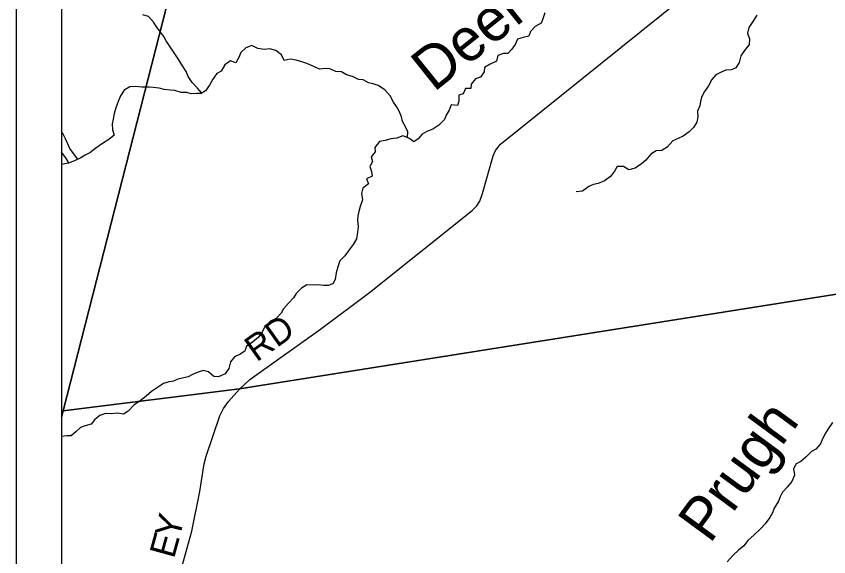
# Model space of a CAD drawing. Extents: x 0 to 36.5, y 0 to 25.3.
# Drawn here: x 2 to 3.798, y 15.97 to 17.166 of the extents above; entities that cross this region are included whole.
import ezdxf

# ---------------------------------------------------------------- set-up
doc = ezdxf.new("R2010")
doc.units = 0
for name, color, linetype in [('DV_X_Township_Line', 7, 'Continuous'), ('GM_X_Interstate_Route', 7, 'Continuous'), ('GM_X_Major_River', 7, 'Continuous'), ('GM_X_Major_River_Text', 7, 'Continuous'), ('GM_X_Minor_River', 7, 'Continuous'), ('GM_X_Minor_River_Text', 7, 'Continuous'), ('GM_X_Township_Road', 7, 'Continuous'), ('GM_X_Township_Road_Text', 7, 'Continuous'), ('SH_Cut_Line', 7, 'Continuous'), ('SH_Data', 7, 'Continuous')]:
    doc.layers.add(name, color=color, linetype=linetype)

msp = doc.modelspace()

# ---------------------------------------------------------------- linework, layer by layer
at = {"layer": 'DV_X_Township_Line'}
msp.add_lwpolyline([(4.5783, 20.9), (3.3366, 20.9), (3.2612, 20.6041), (2.8463, 19.037), (2.6265, 18.2595), (2.5271, 17.8912), (2.5226, 17.8751), (2.5165, 17.8524), (2.5144, 17.8445), (2.4192, 17.4891), (2.3437, 17.2326), (2.3403, 17.2198), (2.1039, 16.2931), (2.4938, 16.3413), (4.0938, 16.595), (4.8891, 16.7511), (5.1383, 16.6527), (6.6079, 15.9978)], dxfattribs=at)
msp.add_lwpolyline([(2.1, 16.2788), (2.1, 14.1), (8.9, 14.1), (8.9, 14.8674), (8.5228, 15.0526), (8.0723, 15.2737), (7.8139, 15.4027), (7.7814, 15.4189), (7.7552, 15.432), (7.703, 15.458), (6.8419, 15.8878), (6.6079, 15.9978), (5.1383, 16.6527), (4.8891, 16.7511), (4.0938, 16.595), (2.4938, 16.3413), (2.1039, 16.2931)], close=True, dxfattribs=at)
at = {"layer": 'GM_X_Interstate_Route'}
msp.add_lwpolyline([(2.1, 17.5234), (2.1, 16.2788), (2.1039, 16.2931), (2.3403, 17.2198), (2.3437, 17.2326), (2.4192, 17.4891)], close=True, dxfattribs=at)
at = {"layer": 'GM_X_Major_River'}
msp.add_lwpolyline([(3.1697, 17.174), (3.1651, 17.1608), (3.1612, 17.1509), (3.1482, 17.1434), (3.1375, 17.1329), (3.134, 17.1223), (3.1214, 17.119), (3.1089, 17.1153), (3.1038, 17.1039), (3.0965, 17.0937), (3.0877, 17.0839), (3.0782, 17.0836), (3.0653, 17.0796), (3.0622, 17.0671), (3.0484, 17.0603), (3.0362, 17.0532), (3.0354, 17.043), (3.0269, 17.0317), (3.0163, 17.0276), (3.0063, 17.0163), (3.0058, 17.0064), (2.9937, 17.0065), (2.9887, 16.9944), (2.9788, 16.9914), (2.979, 16.9785), (2.9759, 16.9687), (2.9623, 16.9703), (2.958, 16.9585), (2.951, 16.9476), (2.9472, 16.9377), (2.9349, 16.9253), (2.9216, 16.9167), (2.9082, 16.9115), (2.8979, 16.9051), (2.8895, 16.8953), (2.8796, 16.8882), (2.8683, 16.8966), (2.855, 16.9013), (2.8417, 16.8965), (2.8288, 16.8951), (2.8158, 16.8914), (2.8037, 16.8888), (2.7933, 16.8756)], dxfattribs=at)
at = {"layer": 'GM_X_Minor_River'}
for points in [[(2.3241, 17.1245), (2.3101, 17.1427), (2.3041, 17.1523), (2.2928, 17.166), (2.2803, 17.1696)], [(3.6383, 17.1689), (3.6298, 17.155), (3.621, 17.1414), (3.6178, 17.1288), (3.6219, 17.1163), (3.6218, 17.1034), (3.6129, 17.0928), (3.6033, 17.0784), (3.5994, 17.0641), (3.5921, 17.0523), (3.5822, 17.0479), (3.57, 17.0472), (3.5578, 17.0416), (3.5479, 17.0364), (3.5391, 17.0262), (3.5318, 17.0126), (3.5226, 17.0001), (3.516, 16.9873), (3.514, 16.9778), (3.5124, 16.9679), (3.5074, 16.9562), (3.5076, 16.944), (3.5056, 16.9319), (3.4983, 16.9202), (3.4887, 16.9108), (3.4757, 16.9006), (3.4662, 16.8961), (3.4529, 16.8902), (3.4402, 16.8766), (3.428, 16.8691), (3.4159, 16.8681), (3.4037, 16.861), (3.3926, 16.8474), (3.383, 16.8395), (3.3689, 16.8297), (3.3552, 16.8264), (3.3431, 16.8338), (3.3294, 16.8339), (3.3237, 16.8233), (3.3144, 16.8116), (3.3015, 16.8018), (3.2877, 16.7959), (3.2767, 16.7941), (3.2668, 16.7892), (3.2527, 16.7791), (3.239, 16.7773)], [(2.4104, 16.9961), (2.4007, 17.007), (2.3894, 17.0196), (2.3804, 17.033), (2.3756, 17.044), (2.3662, 17.0585), (2.3599, 17.0696), (2.3509, 17.0834), (2.3423, 17.0967), (2.3318, 17.1116), (2.3262, 17.1212), (2.3241, 17.1245)], [(2.8653, 16.8977), (2.8665, 16.9103), (2.8601, 16.9229), (2.8542, 16.9336), (2.852, 16.9439), (2.8475, 16.9564), (2.8416, 16.9664), (2.8348, 16.9759), (2.827, 16.99), (2.8153, 17.0038), (2.801, 17.0134), (2.7893, 17.0166), (2.7791, 17.0193), (2.7677, 17.0255), (2.7571, 17.0263), (2.7439, 17.0329), (2.7303, 17.0364), (2.7197, 17.0434), (2.7068, 17.0442), (2.694, 17.05), (2.6845, 17.0509), (2.6712, 17.0491), (2.6583, 17.0553), (2.6425, 17.0619), (2.6315, 17.0658), (2.6194, 17.0693), (2.6058, 17.0717), (2.5928, 17.0684), (2.5865, 17.0806), (2.5744, 17.0909), (2.5612, 17.0941), (2.549, 17.0931), (2.5346, 17.0947), (2.5214, 17.1013), (2.5081, 17.0961), (2.497, 17.0863), (2.4923, 17.0749), (2.4858, 17.0636), (2.4737, 17.0679), (2.4615, 17.0589), (2.4537, 17.0449), (2.4438, 17.0396), (2.435, 17.0268), (2.4273, 17.0136), (2.4188, 17.0011), (2.4093, 16.9955), (2.3998, 16.9956), (2.3873, 16.9949), (2.3774, 16.9977), (2.3645, 16.9978), (2.3505, 17.0021), (2.3411, 17.0025), (2.3274, 17.0042), (2.3161, 17.0069), (2.3032, 17.0086), (2.2939, 17.0097)], [(2.2939, 17.0097), (2.2779, 17.0097), (2.2646, 17.0105), (2.251, 17.0099), (2.2384, 17.0024), (2.2303, 16.9903), (2.2257, 16.9778), (2.2206, 16.9638), (2.2167, 16.9509), (2.2147, 16.9384), (2.2124, 16.9281), (2.2127, 16.9152), (2.2164, 16.903), (2.2049, 16.8936), (2.1908, 16.885), (2.1763, 16.8741), (2.1626, 16.8643), (2.1526, 16.8587), (2.1412, 16.8519), (2.1286, 16.846), (2.1157, 16.8411), (2.1039, 16.8386), (2.1, 16.8378)], [(2.1363, 16.8496), (2.1291, 16.8596), (2.1186, 16.8734), (2.1134, 16.8852), (2.1089, 16.8951), (2.1041, 16.9054), (2.1, 16.9113)], [(2.7933, 16.8756), (2.794, 16.8661), (2.7855, 16.8548), (2.7885, 16.8445), (2.7819, 16.8339), (2.7856, 16.8225), (2.7874, 16.8126), (2.7745, 16.8067), (2.7793, 16.7952), (2.7671, 16.7855), (2.7639, 16.7737), (2.7657, 16.7596), (2.761, 16.7453), (2.7579, 16.7343), (2.7555, 16.7248), (2.7551, 16.7153), (2.7561, 16.7001), (2.7548, 16.6883), (2.7524, 16.6739), (2.7451, 16.6611), (2.734, 16.646), (2.7267, 16.6362), (2.7156, 16.6249), (2.7117, 16.6116), (2.7077, 16.598), (2.7053, 16.5839), (2.7007, 16.5741), (2.6897, 16.57), (2.6802, 16.5701), (2.6669, 16.5714), (2.6567, 16.5707), (2.6426, 16.5716), (2.6312, 16.5644), (2.6189, 16.5528), (2.6131, 16.5426), (2.602, 16.5309), (2.5913, 16.5188), (2.5863, 16.509), (2.5752, 16.4969), (2.5622, 16.491), (2.5496, 16.4789), (2.5426, 16.465), (2.535, 16.4551), (2.5216, 16.4439), (2.5094, 16.4356), (2.5055, 16.4246), (2.4929, 16.4168), (2.4834, 16.4131), (2.4738, 16.4014), (2.4702, 16.3866), (2.4625, 16.3745), (2.4473, 16.3682), (2.4374, 16.3686), (2.4254, 16.3794), (2.4133, 16.3821), (2.4, 16.3777), (2.3901, 16.3732), (2.3801, 16.3684), (2.3573, 16.3629), (2.3478, 16.3588), (2.3379, 16.3573), (2.3254, 16.3536), (2.3124, 16.3446), (2.2994, 16.3353), (2.2876, 16.3251), (2.2742, 16.3146), (2.2601, 16.3056), (2.2474, 16.292), (2.2375, 16.2853), (2.2242, 16.2877), (2.2117, 16.2859), (2.1977, 16.2868), (2.1847, 16.2823), (2.174, 16.2733), (2.166, 16.2631), (2.1523, 16.2594), (2.1424, 16.2557), (2.1328, 16.2471), (2.1217, 16.2377), (2.1122, 16.2374), (2.1, 16.2357)], [(2.1166, 16.8415), (2.1097, 16.8529), (2.1, 16.8651)], [(3.8059, 16.2667), (3.7963, 16.2531), (3.7905, 16.2433), (3.7839, 16.2305), (3.7796, 16.2199), (3.7693, 16.2078), (3.759, 16.203), (3.7468, 16.1905), (3.7357, 16.1808), (3.7254, 16.1752), (3.7196, 16.1642), (3.7221, 16.1501), (3.7159, 16.1361), (3.7059, 16.1248), (3.6952, 16.1124), (3.6902, 16.1026), (3.6867, 16.0927), (3.6767, 16.0772), (3.6728, 16.067), (3.6674, 16.0564), (3.6567, 16.0425), (3.6463, 16.0315), (3.6325, 16.0184), (3.6184, 16.006), (3.6096, 15.9939), (3.5977, 15.9845), (3.5862, 15.9732), (3.5728, 15.9585)]]:
    msp.add_lwpolyline(points, dxfattribs=at)
at = {"layer": 'GM_X_Township_Road'}
for points in [[(2.5272, 16.3696), (2.6732, 16.4737), (2.7817, 16.5545), (3.0089, 16.7361), (3.0189, 16.7463), (3.0254, 16.7567), (3.0317, 16.7741), (3.055, 16.8575), (3.0601, 16.8689), (3.0713, 16.8835), (3.5173, 17.2429), (3.5586, 17.2771), (3.5726, 17.2899), (3.5758, 17.292)], [(2.494, 16.3408), (2.5166, 16.3621), (2.5272, 16.3696)], [(2.1961, 15.6605), (2.2376, 15.7131), (2.2696, 15.7589), (2.3252, 15.8486), (2.3463, 15.8865), (2.3626, 15.9333), (2.3881, 16.0266), (2.4061, 16.1141), (2.4156, 16.1754), (2.4201, 16.1926), (2.4502, 16.2815), (2.4585, 16.2981), (2.4693, 16.3132), (2.494, 16.3408)]]:
    msp.add_lwpolyline(points, dxfattribs=at)
at = {"layer": 'SH_Cut_Line'}
msp.add_lwpolyline([(3.3366, 20.9), (2.1, 20.9), (2.1, 16.2788), (2.1039, 16.2931), (2.3403, 17.2198), (2.3437, 17.2326), (2.4192, 17.4891), (2.5144, 17.8445), (2.5165, 17.8524), (2.5226, 17.8751), (2.5271, 17.8912), (2.6265, 18.2595), (2.8463, 19.037), (3.2612, 20.6041)], close=True, dxfattribs=at)
msp.add_lwpolyline([(4.4591, 20.9), (3.3366, 20.9), (3.2612, 20.6041), (2.8463, 19.037), (2.6265, 18.2595), (2.5271, 17.8912), (2.5226, 17.8751), (2.5165, 17.8524), (2.5144, 17.8445), (2.4192, 17.4891), (2.3437, 17.2326), (2.3403, 17.2198), (2.1039, 16.2931), (2.1, 16.2788), (2.1, 14.1), (8.9, 14.1), (8.9, 20.9), (6.1845, 20.9)], dxfattribs=at)
at = {"layer": 'SH_Data'}
for p, q in [((2, 21), (2, 14)), ((2.1, 20.9), (2.1, 14.1))]:
    msp.add_line(p, q, dxfattribs=at)

# ---------------------------------------------------------------- texts
at = {"layer": 'GM_X_Major_River_Text'}
msp.add_text('Deer', height=0.09472, rotation=38.682, dxfattribs=at).set_placement((2.9237, 16.9969))
at = {"layer": 'GM_X_Minor_River_Text'}
msp.add_text('Prugh', height=0.0947, rotation=53.6732, dxfattribs=at).set_placement((3.5346, 15.9966))
at = {"layer": 'GM_X_Township_Road_Text'}
for s, height, rotation, p in [('RD', 0.05682, 35.4785, (2.5317, 16.3997)), ('Y', 0.0568, 76.4391, (2.3606, 16.0069)), ('E', 0.0568, 74.5533, (2.3488, 15.9639))]:
    msp.add_text(s, height=height, rotation=rotation, dxfattribs=at).set_placement(p)

doc.saveas('drawing.dxf')
